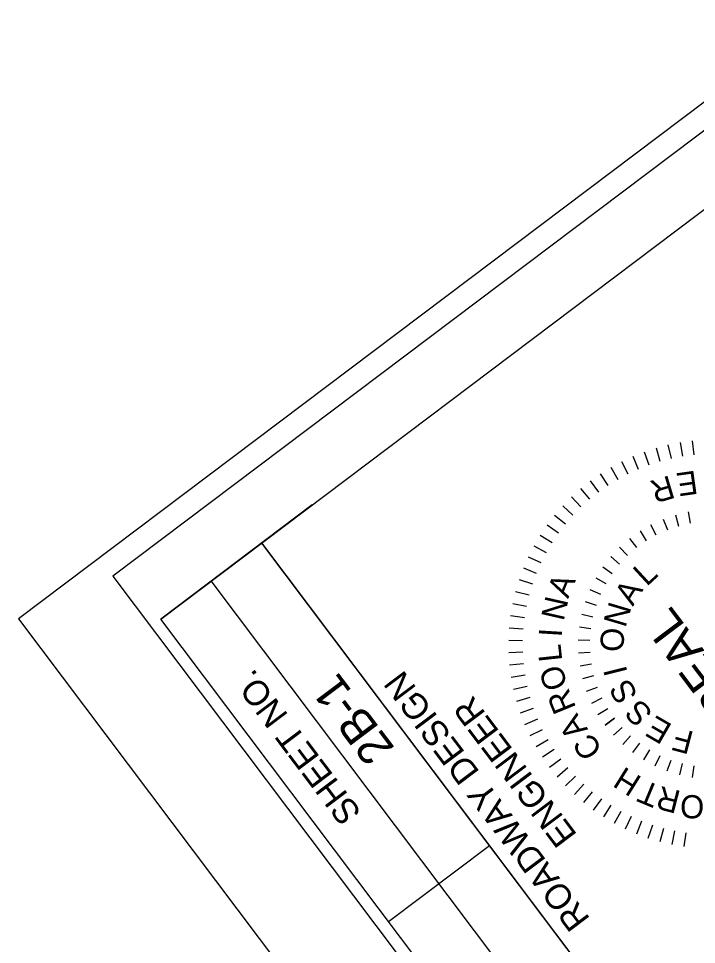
# Model space of a CAD drawing. Extents: x 1262861 to 1264804, y 775326 to 777329.
# Drawn here: x 1262916.5 to 1263050.9, y 776605.9 to 776789.4 of the extents above; entities that cross this region are included whole.
import ezdxf

# ---------------------------------------------------------------- set-up
doc = ezdxf.new("R2010")
doc.units = 0
for name, color, linetype in [('Default', 7, 'Continuous'), ('Sheet Data Field CELL', 7, 'Continuous'), ('Sheet Plan CELL', 7, 'Continuous'), ('Sheet Plot Border Inside CELL', 7, 'Continuous'), ('Sheet Plot Border Outside CELL', 7, 'Continuous'), ('Sheet Typical CELL', 7, 'Continuous')]:
    doc.layers.add(name, color=color, linetype=linetype)

msp = doc.modelspace()

# ---------------------------------------------------------------- linework, layer by layer
at = {"layer": 'Default'}
for p, q in [((1263042.86, 776704.3), (1263043.63, 776701.65)), ((1263045.23, 776704.91), (1263045.84, 776702.22)), ((1263047.63, 776705.38), (1263048.08, 776702.65)), ((1263050.06, 776705.7), (1263050.33, 776702.95)), ((1263038.26, 776702.66), (1263039.34, 776700.12)), ((1263040.54, 776703.55), (1263041.47, 776700.95)), ((1263033.89, 776700.47), (1263035.27, 776698.08)), ((1263036.04, 776701.63), (1263037.27, 776699.16)), ((1263031.81, 776699.18), (1263033.33, 776696.88)), ((1263029.81, 776697.77), (1263031.47, 776695.57)), ((1263027.9, 776696.25), (1263029.68, 776694.14)), ((1263026.08, 776694.6), (1263027.99, 776692.62)), ((1263024.37, 776692.86), (1263026.4, 776690.99)), ((1263049.22, 776691.64), (1263049.64, 776689.38)), ((1263022.77, 776691.01), (1263024.9, 776689.27)), ((1263044.27, 776690.21), (1263045.12, 776688.07)), ((1263046.71, 776691.04), (1263047.35, 776688.83)), ((1263021.28, 776689.07), (1263023.52, 776687.46)), ((1263039.69, 776687.85), (1263040.93, 776685.92)), ((1263042.9, 776687.05), (1263041.84, 776689.1)), ((1263019.91, 776687.05), (1263022.25, 776685.57)), ((1263037.59, 776686.35), (1263039.02, 776684.55)), ((1263018.67, 776684.94), (1263021.09, 776683.61)), ((1263035.65, 776684.65), (1263037.24, 776682.99)), ((1263017.55, 776682.76), (1263020.05, 776681.58)), ((1263033.88, 776682.78), (1263035.62, 776681.28)), ((1263016.57, 776680.52), (1263019.13, 776679.49)), ((1263032.3, 776680.74), (1263034.18, 776679.42)), ((1263030.92, 776678.56), (1263032.92, 776677.43)), ((1263015.73, 776678.22), (1263018.35, 776677.35)), ((1263015.03, 776675.88), (1263017.69, 776675.17)), ((1263029.76, 776676.26), (1263031.86, 776675.33)), ((1263014.47, 776673.5), (1263017.17, 776672.95)), ((1263028.82, 776673.86), (1263031.01, 776673.13)), ((1263014.05, 776671.09), (1263016.78, 776670.7)), ((1263028.13, 776671.37), (1263030.37, 776670.86)), ((1263013.78, 776668.66), (1263016.53, 776668.44)), ((1263027.67, 776668.84), (1263029.96, 776668.54)), ((1263013.66, 776666.22), (1263016.41, 776666.16)), ((1263027.46, 776666.27), (1263029.77, 776666.19)), ((1263013.68, 776663.77), (1263016.44, 776663.88)), ((1263027.51, 776663.69), (1263029.8, 776663.84)), ((1263013.85, 776661.33), (1263016.6, 776661.61)), ((1263027.8, 776661.13), (1263030.07, 776661.5)), ((1263014.17, 776658.91), (1263016.9, 776659.35)), ((1263028.33, 776658.6), (1263030.56, 776659.19)), ((1263014.64, 776656.51), (1263017.33, 776657.12)), ((1263029.11, 776656.14), (1263031.27, 776656.94)), ((1263015.25, 776654.14), (1263017.9, 776654.91)), ((1263030.12, 776653.77), (1263032.19, 776654.78)), ((1263016, 776651.81), (1263018.6, 776652.74)), ((1263031.36, 776651.51), (1263033.32, 776652.71)), ((1263032.81, 776649.38), (1263034.64, 776650.76)), ((1263034.64, 776650.76), (1263032.81, 776649.38)), ((1263016.89, 776649.53), (1263019.43, 776650.62)), ((1263034.46, 776647.39), (1263036.15, 776648.94)), ((1263017.92, 776647.31), (1263020.38, 776648.55)), ((1263036.28, 776645.58), (1263037.83, 776647.29)), ((1263019.08, 776645.16), (1263021.46, 776646.54)), ((1263038.28, 776643.95), (1263039.65, 776645.8)), ((1263020.36, 776643.08), (1263022.66, 776644.6)), ((1263040.43, 776642.51), (1263041.61, 776644.49)), ((1263042.7, 776641.3), (1263043.69, 776643.38)), ((1263021.77, 776641.08), (1263023.98, 776642.74)), ((1263045.08, 776640.31), (1263045.87, 776642.47)), ((1263047.55, 776639.55), (1263048.12, 776641.78)), ((1263023.3, 776639.17), (1263025.41, 776640.96)), ((1263050.07, 776639.04), (1263050.42, 776641.31)), ((1263024.94, 776637.36), (1263026.93, 776639.27)), ((1263026.69, 776635.65), (1263028.56, 776637.67)), ((1263028.53, 776634.04), (1263030.28, 776636.18)), ((1263030.48, 776632.55), (1263032.09, 776634.79)), ((1263032.5, 776631.19), (1263033.98, 776633.52)), ((1263034.61, 776629.95), (1263035.94, 776632.36)), ((1263036.79, 776628.83), (1263037.97, 776631.32)), ((1263039.03, 776627.85), (1263040.06, 776630.41)), ((1263041.32, 776627), (1263042.2, 776629.62)), ((1263043.66, 776626.3), (1263044.38, 776628.97)), ((1263046.05, 776625.74), (1263046.6, 776628.44)), ((1263048.46, 776625.32), (1263048.84, 776628.06))]:
    msp.add_line(p, q, dxfattribs=at)
at = {"layer": 'Sheet Plan CELL'}
msp.add_lwpolyline([(1263054.56, 776753.11), (1263133.61, 776648.16), (1263043.77, 776580.5), (1262964.72, 776685.44)], dxfattribs=at)
msp.add_lwpolyline([(1263054.56, 776753.11), (1263133.61, 776648.16), (1263043.77, 776580.5), (1262964.72, 776685.44)], dxfattribs=at)
at = {"layer": 'Sheet Plot Border Inside CELL'}
msp.add_lwpolyline([(1264780.22, 775982.89), (1263777.88, 777313.61), (1262935.19, 776678.9), (1263937.52, 775348.16)], close=True, dxfattribs=at)
at = {"layer": 'Sheet Plot Border Outside CELL'}
msp.add_lwpolyline([(1262916.5, 776670.46), (1263929.36, 775325.74), (1264804.01, 775984.53), (1263791.15, 777329.26)], close=True, dxfattribs=at)
at = {"layer": 'Sheet Typical CELL'}
for p, q in [((1262944.69, 776670.41), (1263783.4, 777302.14)), ((1262974.7, 776693.01), (1262944.69, 776670.41)), ((1263085.07, 776525.72), (1262964.72, 776685.5)), ((1263075.06, 776518.17), (1262954.71, 776677.96)), ((1263065.04, 776510.63), (1262944.69, 776670.41)), ((1263847.15, 775472.26), (1262944.69, 776670.41)), ((1262989.84, 776610.48), (1263009.87, 776625.57))]:
    msp.add_line(p, q, dxfattribs=at)

# ---------------------------------------------------------------- texts
at = {"layer": 'Default'}
for s, height, rotation, p in [('R', 4.6, 196.6068, (1263045.61, 776698.92)), ('E', 4.6, 187.9341, (1263050.75, 776699.82)), ('L', 4.6, 42.805, (1263041.01, 776676.74)), ('A', 4.6, 67.4515, (1263025.43, 776674.34)), ('A', 4.6, 58.1013, (1263038.27, 776672.81)), ('N', 4.6, 77.219, (1263024.54, 776669.87)), ('N', 4.6, 73.3975, (1263036.78, 776668.54)), ('SEAL', 6.899, 126.9344, (1263059.91, 776654.29)), ('I', 4.6, 86.5135, (1263024.19, 776666.73)), ('O', 4.6, 88.6938, (1263036.44, 776663.86)), ('L', 4.6, 96.089, (1263024.29, 776662.17)), ('O', 4.6, 109.2252, (1263025.46, 776657.2)), ('I', 4.6, 103.99, (1263037.24, 776659.82)), ('S', 4.6, 119.2863, (1263039.38, 776655.32)), ('R', 4.6, 112.2821, (1263027.08, 776652.84)), ('S', 4.6, 134.5825, (1263042.45, 776651.88)), ('A', 4.6, 124.2914, (1263029.46, 776648.54)), ('E', 4.6, 149.8788, (1263046.3, 776649.38)), ('C', 4.6, 124.2914, (1263032.41, 776644.47)), ('F', 4.6, 165.175, (1263050.59, 776648)), ('H', 4.6, 148.0021, (1263040.26, 776638.94)), ('T', 4.6, 157.434, (1263044.09, 776637.18)), ('R', 4.6, 165.595, (1263048, 776636.26)), ('O', 4.6, 178.6517, (1263052.47, 776635.46))]:
    msp.add_text(s, height=height, rotation=rotation, dxfattribs=at).set_placement(p)
at = {"layer": 'Sheet Data Field CELL'}
msp.add_text('2B-1', height=6.748, rotation=126.9874, dxfattribs=at).set_placement((1262991.2, 776644.82))
at = {"layer": 'Sheet Plan CELL'}
for s, height, p in [('SHEET NO.', 5, (1262984.64, 776632.04)), ('ROADWAY DESIGN', 4.9986, (1263029.94, 776610.99)), ('ENGINEER', 4.999, (1263027.36, 776627.63))]:
    msp.add_text(s, height=height, rotation=126.9874, dxfattribs=at).set_placement(p)

doc.saveas('drawing.dxf')
